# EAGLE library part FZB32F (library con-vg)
CONNECTOR female, 32 pins, type F, rows BZ, grid 5.08 mm
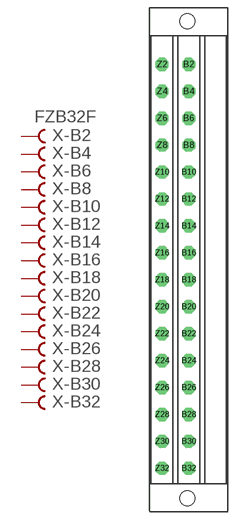
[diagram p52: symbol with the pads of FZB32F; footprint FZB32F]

Designator prefix X; gates -B2=FVAL -B4=FEM -B6=FEM -B8=FEM -B10=FEM -B12=FEM -B14=FEM -B16=FEM -B18=FEM -B20=FEM -B22=FEM -B24=FEM -B26=FEM -B28=FEM -B30=FEM -B32=FEM -Z2=FVAL -Z4=FEM -Z6=FEM -Z8=FEM -Z10=FEM -Z12=FEM -Z14=FEM -Z16=FEM -Z18=FEM -Z20=FEM -Z22=FEM -Z24=FEM -Z26=FEM -Z28=FEM -Z30=FEM -Z32=FEM

## FZB32F  [FZB32F]
B2  -B2:B  pas
B4  -B4:B  pas
B6  -B6:B  pas
B8  -B8:B  pas
B10  -B10:B  pas
B12  -B12:B  pas
B14  -B14:B  pas
B16  -B16:B  pas
B18  -B18:B  pas
B20  -B20:B  pas
B22  -B22:B  pas
B24  -B24:B  pas
B26  -B26:B  pas
B28  -B28:B  pas
B30  -B30:B  pas
B32  -B32:B  pas
Z2  -Z2:B  pas
Z4  -Z4:B  pas
Z6  -Z6:B  pas
Z8  -Z8:B  pas
Z10  -Z10:B  pas
Z12  -Z12:B  pas
Z14  -Z14:B  pas
Z16  -Z16:B  pas
Z18  -Z18:B  pas
Z20  -Z20:B  pas
Z22  -Z22:B  pas
Z24  -Z24:B  pas
Z26  -Z26:B  pas
Z28  -Z28:B  pas
Z30  -Z30:B  pas
Z32  -Z32:B  pas

## Footprint FZB32F (pad centres in mm)
CONNECTOR female, 32 pins, type F, rows BZ, grid 5.08 mm
drill 1.676 octagon: B2 0,36.855; B4 0,31.775; B6 0,26.695; B8 0,21.615; B10 0,16.535; B12 0,11.455; B14 0,6.375; B16 0,1.295; B18 0,-3.785; B20 0,-8.865; B22 0,-13.945; B24 0,-19.025; B26 0,-24.105; B28 0,-29.185; B30 0,-34.265; B32 0,-39.345; Z2 -5.08,36.855; Z4 -5.08,31.775; Z6 -5.08,26.695; Z8 -5.08,21.615; Z10 -5.08,16.535; Z12 -5.08,11.455; Z14 -5.08,6.375; Z16 -5.08,1.295; Z18 -5.08,-3.785; Z20 -5.08,-8.865; Z22 -5.08,-13.945; Z24 -5.08,-19.025; Z26 -5.08,-24.105; Z28 -5.08,-29.185; Z30 -5.08,-34.265; Z32 -5.08,-39.345
hole 2.794 at -0.305,44.983
hole 2.794 at -0.305,-44.983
